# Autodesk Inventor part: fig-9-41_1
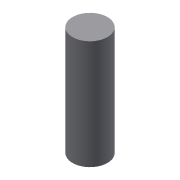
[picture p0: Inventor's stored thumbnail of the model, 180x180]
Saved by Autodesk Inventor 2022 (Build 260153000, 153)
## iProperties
Created: 2013-03
Part Number: fig-9-41_1
Material: Generic
Document SubType Name: Modeling
Designer: CADCIM
Density: 1 g/cm^3
Appearance: Default
Author: CADCIM
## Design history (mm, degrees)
sketch "Sketch1"
  geometry: C1 r 4 at (0, 0); 1 further point
  constraints: 1 centre point, 1 coincident
  dimensions: "d0" = 8 diameter of C1
extrude "Extrusion1" new body sketch "Sketch1" stored distance "d2" = 25; taper "d3" = 0 deg
body "Solid1"
